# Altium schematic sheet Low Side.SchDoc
size 431 x 279 mm; Date: Not shown in title block; ApprovedBy: Not shown in title block; CheckedBy: Not shown in title block; Author: Not shown in title block; CompanyName: Not shown in title block; Engineer: Not shown in title block; Organization: Not shown in title block; Address1: Not shown in title block; Address2: Not shown in title block; Address3: Not shown in title block; Address4: Not shown in title block; DocumentNumber: 4; Revision: Use project parameter SCH_Rev; SheetNumber: 4; SheetTotal: 5; PageSetup: Record=PageOptions¦CenterHorizontal=True¦CenterVertical=True¦PrintScale=1.00¦XCorrection=1.00¦YCorrection=1.00¦PrintKind=0¦BorderSize=5000000¦LeftOffset=0¦BottomOffset=0¦Orientation=2¦PaperLength=1000¦PaperWidth=1000¦Scale=100¦PaperSource=15¦PrintQuality=600¦MediaType=1¦DitherType=10¦PaperKind=Letter¦PrintScaleMode=1
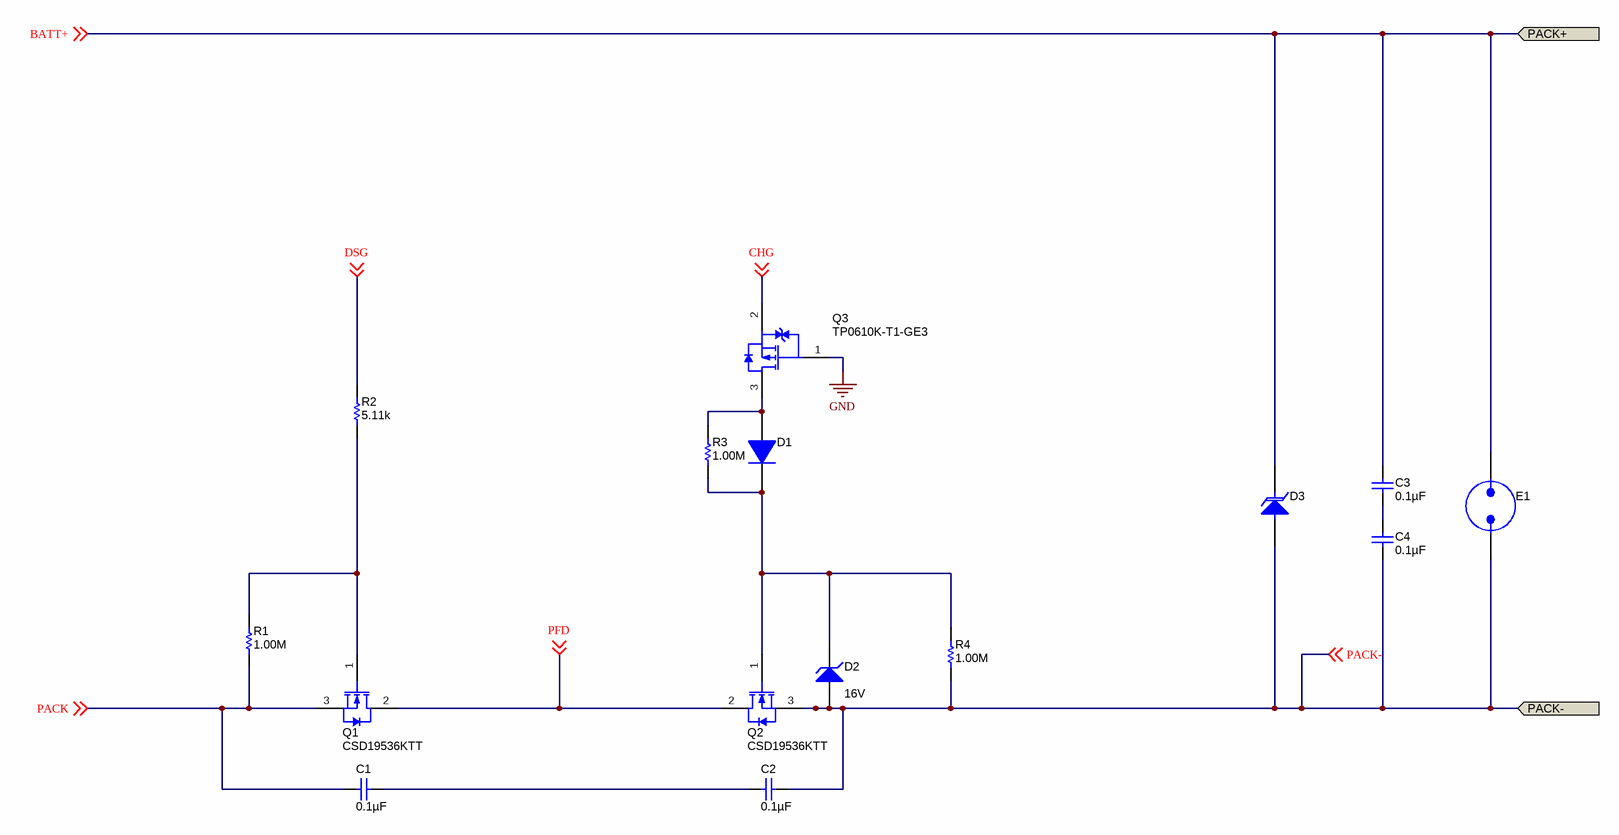
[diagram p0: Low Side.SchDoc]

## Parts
C1  ValueDisplayed: 0.1µF  [0603]  (hidden comment: GRM188R72A104KA35D)
C2  ValueDisplayed: 0.1µF  [0603]  (hidden comment: GRM188R72A104KA35D)
C3  ValueDisplayed: 0.1µF  [0603]  (hidden comment: GRM188R72A104KA35D)
C4  ValueDisplayed: 0.1µF  [0603]  (hidden comment: GRM188R72A104KA35D)
D1  MMSD914T1G  [SOD-123]  (value not drawn)
D2  value 16V  [SOD-123]  (hidden comment: MMSZ5246B-7-F)
D3  SMCJ160A-TP  [SMC_265]  (value not drawn)
E1  N/A  [SPARK_GAP2]  (value not drawn)  (no BOM)
Q1  CSD19536KTT  [KTT0002A_N]
Q2  CSD19536KTT  [KTT0002A_N]
Q3  TP0610K-T1-GE3  [SOT-23]
R1  ValueDisplayed: 1.00M  [0603]  (hidden comment: CRCW06031M00FKEA)
R2  ValueDisplayed: 5.11k  [0603]  (hidden comment: RT0603DRE075K11L)
R3  ValueDisplayed: 1.00M  [0603]  (hidden comment: CRCW06031M00FKEA)
R4  ValueDisplayed: 1.00M  [0603]  (hidden comment: CRCW06031M00FKEA)

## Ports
PACK+, PACK-

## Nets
GND: Q3.1(G)
BATT+: C3.2 D3.1(K) E1.2 ; off-sheet BATT+, port PACK+
CHG: Q3.2(S) ; off-sheet CHG
DSG: R2.2 ; off-sheet DSG
PACK: C1.2 Q1.3(S) R1.1 ; off-sheet PACK
PACK-: C2.1 C4.1 D2.2(A) D3.2(A) E1.1 Q2.3(S) R4.1 ; off-sheet PACK-, port PACK-
PFD: Q1.2(D) Q2.2(D) ; off-sheet PFD
NetC1_1: C1.1 C2.2
NetC3_1: C3.1 C4.2
NetD1_1: D1.1(K) D2.1(K) Q2.1(G) R3.1 R4.2
NetD1_2: D1.2(A) Q3.3(D) R3.2
NetQ1_1: Q1.1(G) R1.2 R2.1

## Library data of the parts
C1-C4 = GRM188R72A104KA35D: CAP, CERM, 0.1uF, 100V, +/-10%, X7R, 0603; Manufacturer: MuRata; Polarized: N; CompType: Capacitor; U/M: EA; Cap_F: 0.0000001; Tolerance_%: 10; Value1: Unknown; VDC_V: 100; TaMin_C: -55; TaMax_C: 125
D1 = MMSD914T1G: Diode, Switching, 100 V, 0.2 A, SOD-123; Manufacturer: ON Semiconductor; U/M: EA; Value: 100V; Value1: 0.2A; Io_A: 0.2; Vr_V: 100; TJmax_C: 150
D2 = MMSZ5246B-7-F: Diode, Zener, 16V, 500mW, SOD-123; Manufacturer: Diodes Inc.; U/M: EA; Power_W: 0.5; Vz_V: 16; Value1: 0.5W; RJA_CperW: 350
D3 = SMCJ160A-TP: Diode, TVS, Uni, 160 V, 259 Vc, SMC; Manufacturer: Micro Commercial Components; Value: 160V; U/M: EA; Vr_V: 160; Value1: W; SizeAreaWB_mm2: 78.5757; SizeArea_mm2: 46.8857; SizeX_mm: 7.94; SizeY_mm: 5.905; SizeZ_mm: 2.62; AEC Category: Q101; AEC Qualified: N
E1 = SparkGap: Spark Gap; SymbolCreator: a0412235
Q1 Q2 = CSD19536KTT: MOSFET, N-CH, 100 V, 200 A,; Manufacturer: Texas Instruments; Alternate Manufacturer: None; U/M: EA; ChType: N; Value: 100V; VdsMax_V: 100; Value1: ? ohm; Value2: 118 nC; QgTyp_nC: 118; Vgs_V: 20; IdsMax_A: 200
Q3 = TP0610K-T1-GE3: MOSFET, P-CH, -60 V, -0.185 A, SOT-23; Manufacturer: Vishay-Siliconix; Alternate Manufacturer: None; SymbolCreator: a0411947; U/M: EA; ChType: P; Value: -60V; Value1: 10 ohm; Rdson45_ohm: 10; Value2: 1.7 nC; QgTyp_nC: 1.7; Vgs_V: 20
R1 R3 R4 = CRCW06031M00FKEA: RES, 1.00 M, 1%, 0.1 W, 0603; Manufacturer: Vishay-Dale; CompType: Resistor; Value: 1.00Meg; Res_ohm: 1000000; Value_Code: 1M00; Tolerance_%: 1; Power_W: 0.1; Value2: 0.1W; VDC_V: 75; TempCo: 100 ppm/C; EIA_Code: E96; U/M: EA
R2 = RT0603DRE075K11L: RES, 5.11 k, 0.5%, 0.1 W, 0603; Manufacturer: Yageo America; CompType: Resistor; Value: 5.11k; Res_ohm: 5110; Value_Code: 5k11; Tolerance_%: 0.5; Power_W: 0.1; Value2: 0.1W; VDC_V: 75; TempCo: 50 ppm/C; SizeArea_mm2: 1.28; SizeX_mm: 1.6; SizeY_mm: 0.8; SizeZ_mm: 1; EIA_Code: E192; U/M: EA; AEC Category: Q200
